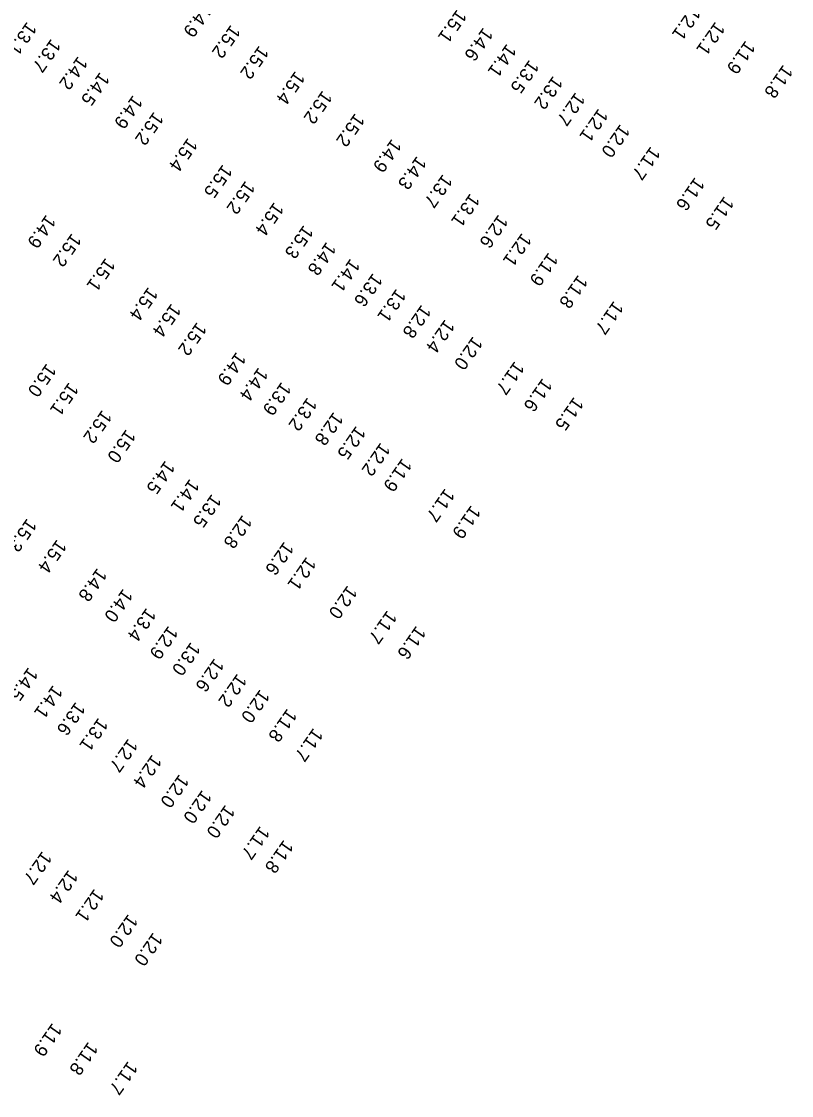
# Model space of a CAD drawing. Extents: x 815385 to 820851, y 582449 to 604245.
# Drawn here: x 816418.2 to 816709.5, y 583543.2 to 583949.5 of the extents above; entities that cross this region are included whole.
import ezdxf

# ---------------------------------------------------------------- set-up
doc = ezdxf.new("R2010")
doc.units = 0
doc.layers.add('V-TOPO-SOUN-101408', color=7, linetype='Continuous')

msp = doc.modelspace()

# ---------------------------------------------------------------- texts
at = {"layer": 'V-TOPO-SOUN-101408'}
for s, p in [('14.9 ', (816486.61, 583956.51)), ('15.1 ', (816582.99, 583954.36)), ('12.1 ', (816671.54, 583955.41)), ('13.1 ', (816420.31, 583949.67)), ('12.1 ', (816680.73, 583949.71)), ('15.2 ', (816497.44, 583948.56)), ('14.6 ', (816592.96, 583947.54)), ('13.7 ', (816429.44, 583943.24)), ('11.9 ', (816692.2, 583942.6)), ('15.2 ', (816508.13, 583940.67)), ('14.1 ', (816601.83, 583941.36)), ('14.2 ', (816439.62, 583936.65)), ('13.5 ', (816610.36, 583935.3)), ('11.8 ', (816706.43, 583933.46)), ('14.5 ', (816447.91, 583930.65)), ('15.4 ', (816521.82, 583931.07)), ('13.2 ', (816619.38, 583929.22)), ('14.9 ', (816460.4, 583921.9)), ('15.2 ', (816532.14, 583923.7)), ('12.7 ', (816627.85, 583923.03)), ('15.2 ', (816468.34, 583915.66)), ('15.2 ', (816544.43, 583915.08)), ('12.1 ', (816636.52, 583916.85)), ('12.0 ', (816644.77, 583911)), ('15.4 ', (816481.19, 583905.75)), ('14.9 ', (816558.34, 583905.38)), ('11.7 ', (816656.29, 583902.54)), ('14.3 ', (816567.82, 583898.88)), ('15.5 ', (816494.37, 583895.72)), ('15.2 ', (816502.98, 583889.54)), ('13.7 ', (816577.64, 583892.02)), ('11.6 ', (816673.03, 583890.9)), ('13.1 ', (816587.98, 583884.73)), ('15.4 ', (816513.83, 583881.44)), ('11.5 ', (816684.12, 583883.68)), ('14.9 ', (816427.58, 583876.71)), ('12.6 ', (816598.69, 583876.75)), ('15.3 ', (816525.01, 583872.76)), ('15.2 ', (816437.25, 583869.66)), ('12.1 ', (816607.56, 583869.78)), ('14.8 ', (816533.64, 583866.41)), ('15.1 ', (816450.06, 583860.37)), ('11.9 ', (816617.62, 583862.39)), ('14.1 ', (816542.67, 583860.09)), ('13.6 ', (816551.19, 583854.6)), ('11.8 ', (816628.84, 583853.92)), ('15.4 ', (816466.21, 583849.34)), ('13.1 ', (816560.06, 583848.71)), ('11.7 ', (816642.34, 583844.1)), ('15.4 ', (816474.95, 583843.12)), ('12.8 ', (816569.57, 583842.65)), ('15.2 ', (816484.62, 583836.05)), ('12.4 ', (816578.47, 583837.11)), ('12.0 ', (816589.04, 583830.67)), ('14.9 ', (816499.54, 583824.79)), ('15.0 ', (816427.74, 583820.44)), ('11.7 ', (816604.84, 583821.29)), ('14.4 ', (816507.9, 583818.91)), ('15.1 ', (816436.18, 583813.28)), ('13.9 ', (816516.62, 583813.44)), ('11.6 ', (816615.38, 583814.86)), ('13.2 ', (816526.43, 583807.57)), ('11.5 ', (816627.24, 583807.75)), ('15.2 ', (816448.77, 583802.85)), ('12.8 ', (816536.32, 583802.08)), ('15.0 ', (816457.82, 583795.51)), ('12.5 ', (816544.84, 583796.8)), ('12.2 ', (816554.09, 583790.5)), ('14.5 ', (816472.64, 583783.71)), ('11.9 ', (816562.28, 583784.58)), ('14.1 ', (816481.89, 583776.75)), ('13.5 ', (816490.22, 583771.02)), ('11.7 ', (816578.48, 583773.17)), ('11.9 ', (816588.34, 583766.78)), ('12.8 ', (816501.84, 583763.11)), ('15.3 ', (816420.34, 583761.8)), ('15.4 ', (816431.64, 583753.85)), ('12.6 ', (816517.62, 583753.02)), ('12.1 ', (816526.07, 583747.27)), ('14.8 ', (816446.91, 583743.03)), ('14.0 ', (816456.69, 583735.21)), ('12.0 ', (816541.6, 583736.47)), ('13.4 ', (816465.51, 583727.97)), ('11.7 ', (816556.62, 583727.02)), ('12.9 ', (816473.83, 583721.19)), ('11.6 ', (816567.59, 583721.19)), ('13.0 ', (816482.3, 583715.01)), ('12.6 ', (816491.22, 583708.87)), ('14.5 ', (816420.84, 583705.48)), ('12.2 ', (816499.85, 583703.07)), ('14.1 ', (816430.18, 583698.75)), ('12.0 ', (816508.47, 583697.12)), ('13.6 ', (816438.74, 583692.39)), ('11.8 ', (816518.79, 583689.87)), ('13.1 ', (816447.34, 583686.4)), ('11.7 ', (816528.69, 583682.52)), ('12.7 ', (816458.6, 583678.5)), ('12.4 ', (816467.65, 583672.45)), ('12.0 ', (816477.93, 583665.01)), ('12.0 ', (816486.57, 583659.06)), ('12.0 ', (816495.36, 583653.48)), ('11.7 ', (816508.52, 583645.45)), ('11.8 ', (816517.46, 583640.23)), ('12.7 ', (816426.09, 583635.95)), ('12.4 ', (816435.99, 583628.86)), ('12.1 ', (816445.8, 583621.71)), ('12.0 ', (816458.62, 583612.13)), ('12.0 ', (816468.03, 583605.16)), ('11.9 ', (816429.9, 583570.93)), ('11.8 ', (816443.51, 583563.81)), ('11.7 ', (816458.52, 583556.46))]:
    msp.add_text(s, height=5, rotation=234.911, dxfattribs=at).set_placement(p)

doc.saveas('drawing.dxf')
